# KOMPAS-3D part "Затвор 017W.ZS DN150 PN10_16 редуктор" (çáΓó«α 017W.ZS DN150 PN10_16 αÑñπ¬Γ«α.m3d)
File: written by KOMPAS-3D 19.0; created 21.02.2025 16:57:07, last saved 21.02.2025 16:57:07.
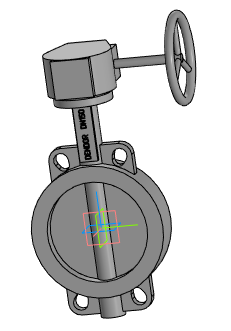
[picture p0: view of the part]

Document properties: Автор: Евгений; Полное имя файла: Затвор 017W.ZS DN150 PN10_16 редуктор.a3d

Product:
- Part/product: Затвор 017W.ZS DN150 PN10_16 редуктор
    Масса: 17.1295

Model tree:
1. Операция без истории:1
